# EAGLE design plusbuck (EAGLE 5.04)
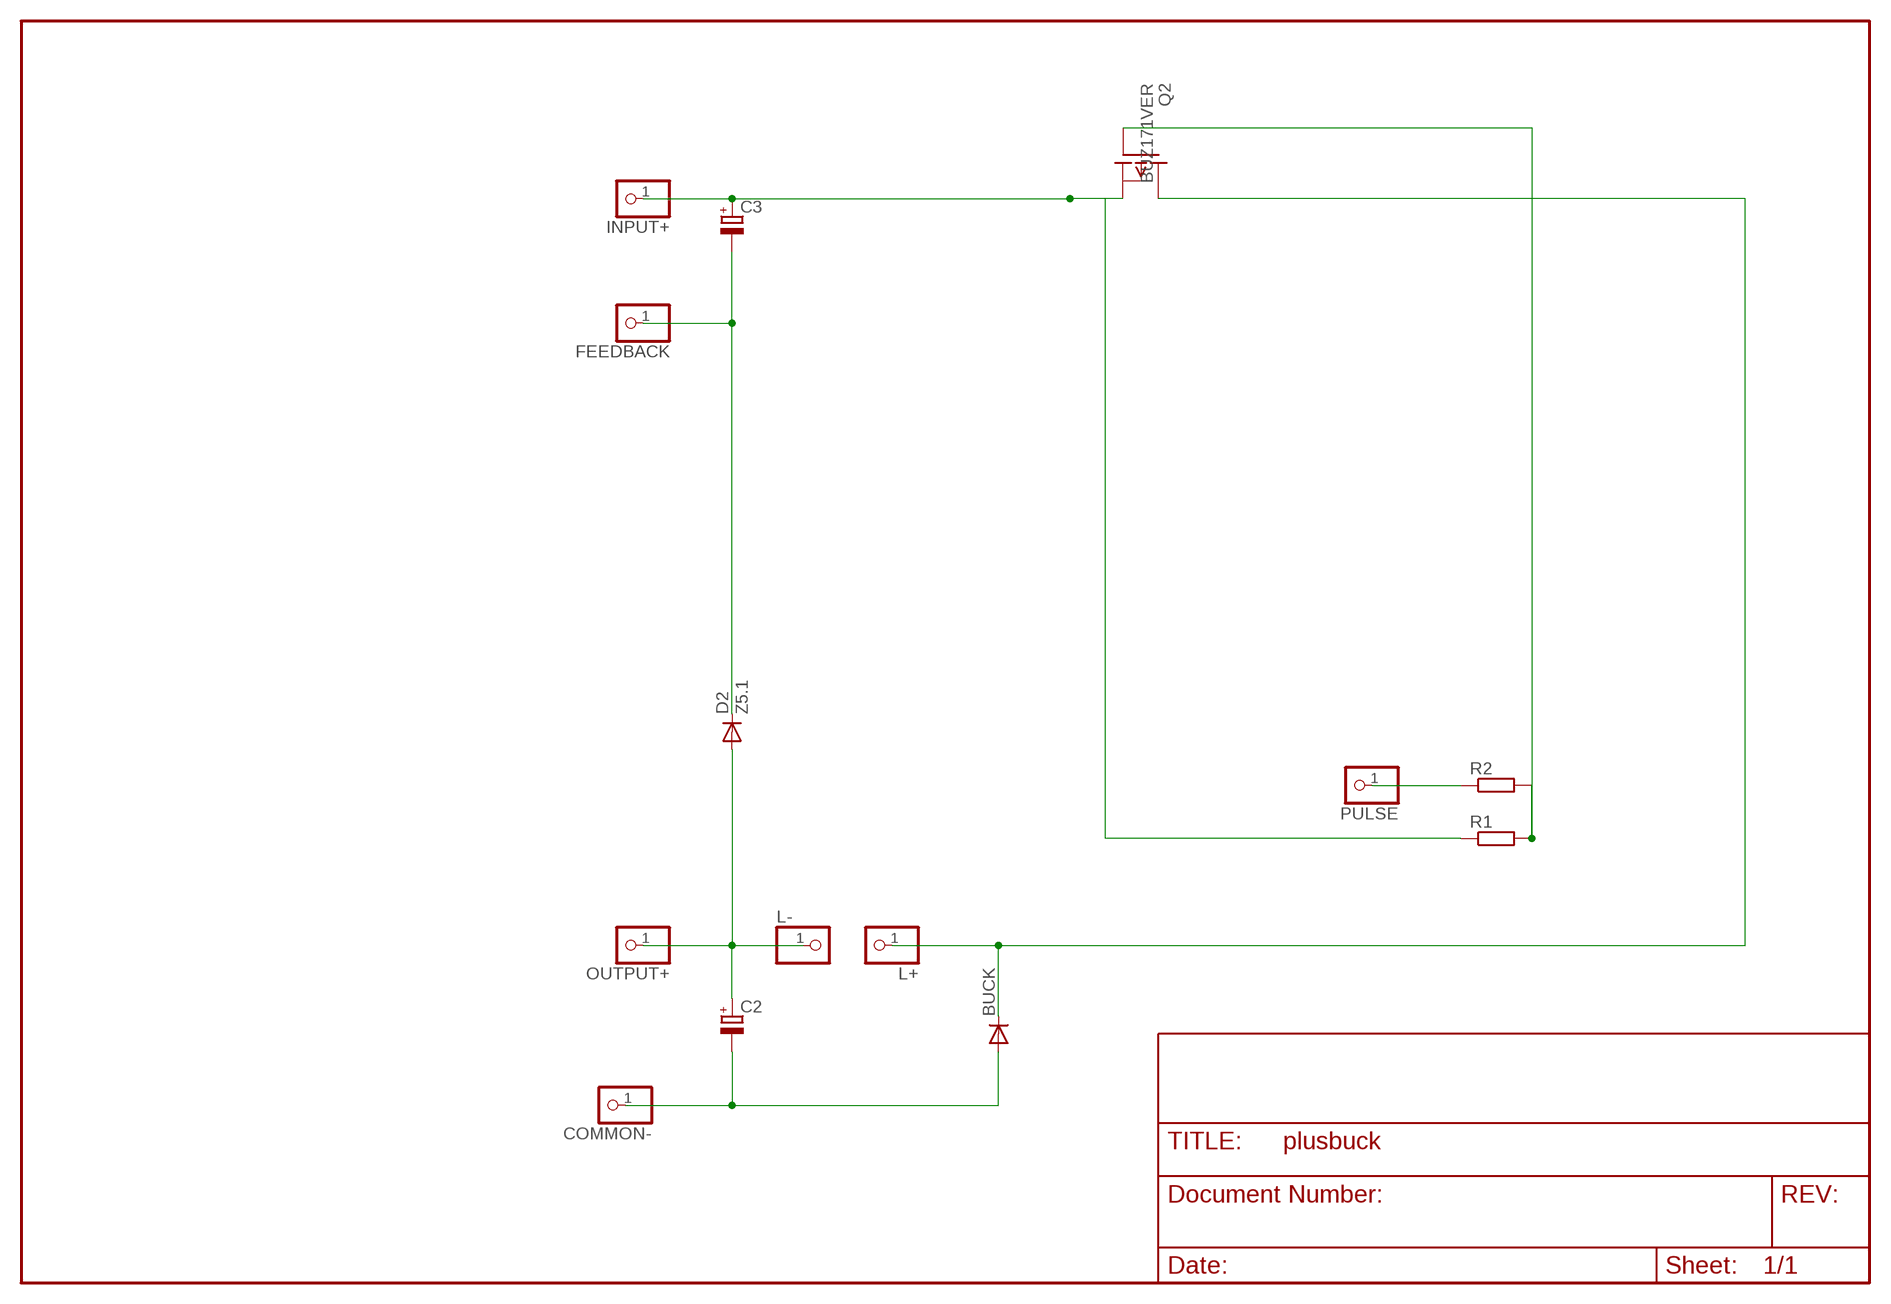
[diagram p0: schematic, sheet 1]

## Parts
BUCK  DIODE-D-10  [D-10]
C2  CPOL-EUE2.5-7  [E2,5-7]
C3  CPOL-EUE2-4  [E2-4]
COMMON-  PINHD-1X1  [1X01]
D2  Z5.1  DIODE-D-7.5  [D-7.5]
FEEDBACK  PINHD-1X1  [1X01]
INPUT+  PINHD-1X1  [1X01]
L+  PINHD-1X1  [1X01]
L-  PINHD-1X1  [1X01]
OUTPUT+  PINHD-1X1  [1X01]
PULSE  PINHD-1X1  [1X01]
Q2  BUZ171VER  [TO220V]
R1  R-EU_0204/2V  [0204V]
R2  R-EU_0204/2V  [0204V]

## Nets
GATE: Q2.1(G) R1.2 R2.2
L+: BUCK.C L+.1 Q2.2(D)
L-: C2.+ D2.A L-.1 OUTPUT+.1
N$2: BUCK.A C2.- COMMON-.1
N$3: PULSE.1 R2.1
N$9: C3.- D2.C FEEDBACK.1
V+: C3.+ INPUT+.1 Q2.3(S) R1.1

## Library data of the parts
BUCK D2 = diode:DIODE-: DIODE
C2 C3 = rcl(2):CPOL-EU: POLARIZED CAPACITOR, European symbol
COMMON- FEEDBACK INPUT+ L+ L- OUTPUT+ PULSE = pinhead:PINHD-1X1: PIN HEADER
Q2 = transistor-fet:BUZ171: P-Channel Enhancement MOSFET -50V; 7A; 0,4Ohm
R1 R2 = rcl-2:R-EU_: RESISTOR, European symbol

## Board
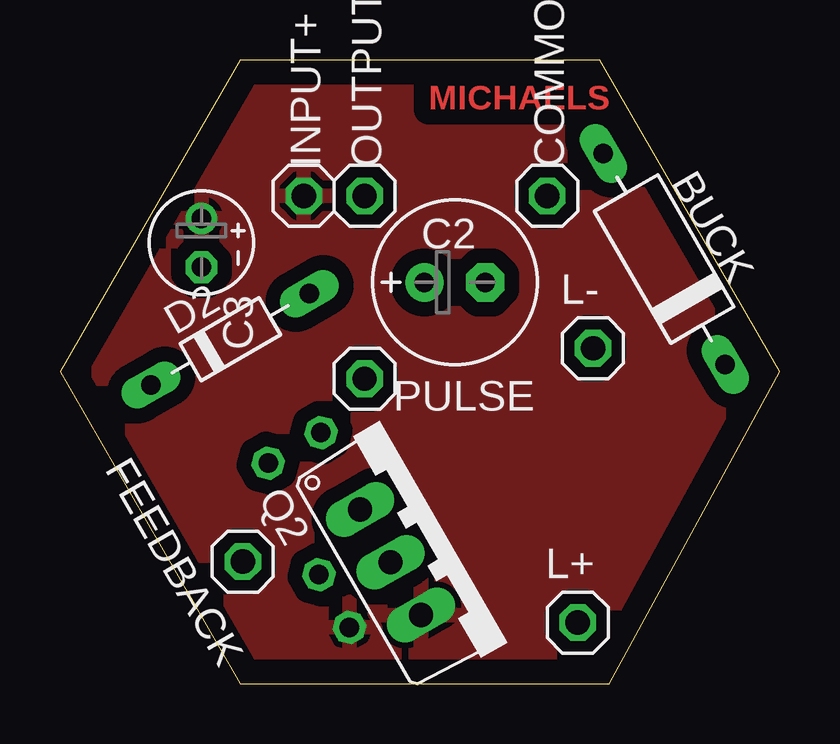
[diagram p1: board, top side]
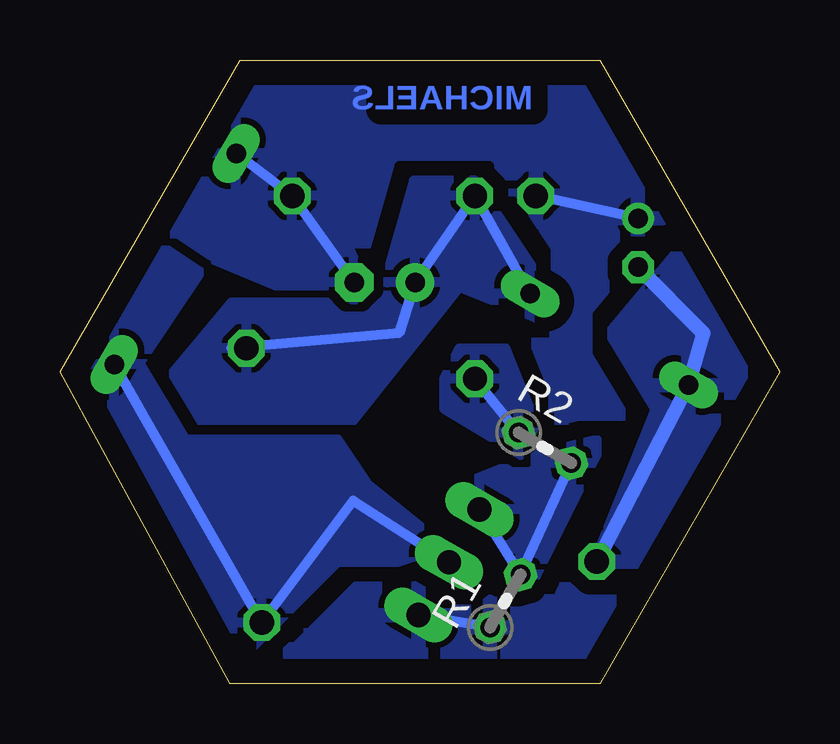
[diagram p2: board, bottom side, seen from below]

Size 30 x 25.98 mm. Coordinates in mm from the lower left corner, seen from the top.
Outline: 7.5,0 22.9,0 30,12.99 22.5,25.98 7.5,25.98 0,12.99 7.5,0
Copper layers (1*16): Top 0.035mm / dielectric 1.5mm / Bottom 0.035mm
Design rules "default": minimum track width 10mil, minimum drill 24mil, track to track 8mil, track to pad 8mil, pad to pad 8mil, via to via 8mil, smd to smd 8mil, copper to edge 40mil, drill to drill 8mil, minimum pad ring 10mil, minimum via ring 8mil, stop-mask expansion 4mil, vias tented up to drill 0mil, thermal gap 10mil

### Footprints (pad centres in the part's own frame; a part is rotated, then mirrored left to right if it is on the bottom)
D-10 = drill 0.813 long: A 5.08,0; C -5.08,0
E2,5-7 = drill 0.813 pad 1.6 round: + -1.27,0 | drill 0.813 pad 1.6 octagon: - 1.27,0
E2-4 = drill 0.813 pad 1.27 round: + -1.016,0 | drill 0.813 pad 1.27 octagon: - 1.016,0
1X01 = drill 1.016 octagon: 1 0,0
D-7.5 = drill 0.813 long: A 3.81,0; C -3.81,0
TO220V = drill 1.016 long: 1 -2.54,-2.54; 2 0,-2.54; 3 2.54,-2.54
0204V = drill 0.813 octagon: 1 -1.27,0; 2 1.27,0

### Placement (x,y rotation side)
BUCK  25.2,17.69 120 top
C2  16.47,16.72 0 top
C3  5.9,18.36 270 top
COMMON-  20.32,20.32 0 top
D2  7.1,14.34 30 top
FEEDBACK  7.62,5.08 0 top
INPUT+  10.16,20.32 0 top
L+  21.59,2.54 0 top
L-  22.23,13.97 0 top
OUTPUT+  12.7,20.32 0 top
PULSE  12.7,12.7 0 top
Q2  15.98,6.32 300 top
R1  11.43,3.43 60 bottom
R2  9.78,9.82 330 bottom

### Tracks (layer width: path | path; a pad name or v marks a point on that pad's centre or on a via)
GATE
  Bottom 0.406: R2.2 R1.2 Q2.1
  pour Bottom (isolate 0.305, rank 2): 7.62,10.16 10.16,9.53 13.34,8.26 10.16,4.45 7.62,9.53
L+
  Bottom 0.406: Q2.2 17.78,7.62 L+.1 BUCK.C
  pour Bottom (isolate 0.406): 13.97,5.71 17.14,8.26 18.41,10.16 24.77,10.16 26.67,13.34 24.13,17.14 26.04,18.41 29.21,12.7 22.23,1.27 18.41,5.08 15.88,5.08
L-
  Bottom 0.406: D2.A OUTPUT+.1 C2.+ 15.88,14.61 22.86,13.97 L-.1
  pour Bottom (isolate 0.406, rank 2): 17.78,15.88 22.86,15.88 26.04,12.06 24.77,10.16 18.41,10.16 13.34,16.51 10.16,15.24 10.16,17.14 12.7,20.95 15.24,20.95 16.51,16.51
N$2
  Bottom 0.406: C2.- COMMON-.1 BUCK.A
  pour Bottom (isolate 0.305, rank 3): 17.78,17.78 20.95,25.4 22.86,24.13 25.4,18.41 17.78,15.24
N$3
  Bottom 0.406: R2.1 PULSE.1
  pour Bottom (isolate 0.406): 13.97,12.7 13.34,13.97 11.43,13.97 10.16,10.79 10.79,9.53 13.97,11.43
N$9
  Bottom 0.61: C3.- 3.17,14.61 D2.C FEEDBACK.1
  pour Bottom (isolate 0.406, rank 2): 7.62,5.08 5.08,5.08 5.08,5.71 2.54,9.53 0,13.97 3.81,18.41 6.99,14.61 5.08,11.43
V+
  Bottom 0.406: R1.1 Q2.3 | C3.+ INPUT+.1
  pour Bottom (isolate 0.61, rank 3): 7.62,25.4 22.23,25.4 29.21,12.7 22.23,0.64 7.62,0.64 1.27,13.34
  pour Top (isolate 0.61, rank 3): 7.62,25.4 22.23,25.4 29.21,12.7 22.23,0.64 7.62,0.64 1.27,13.34

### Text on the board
Top: MICHAELS
Bottom: MICHAELS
